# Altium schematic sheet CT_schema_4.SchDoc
size 316 x 185 mm
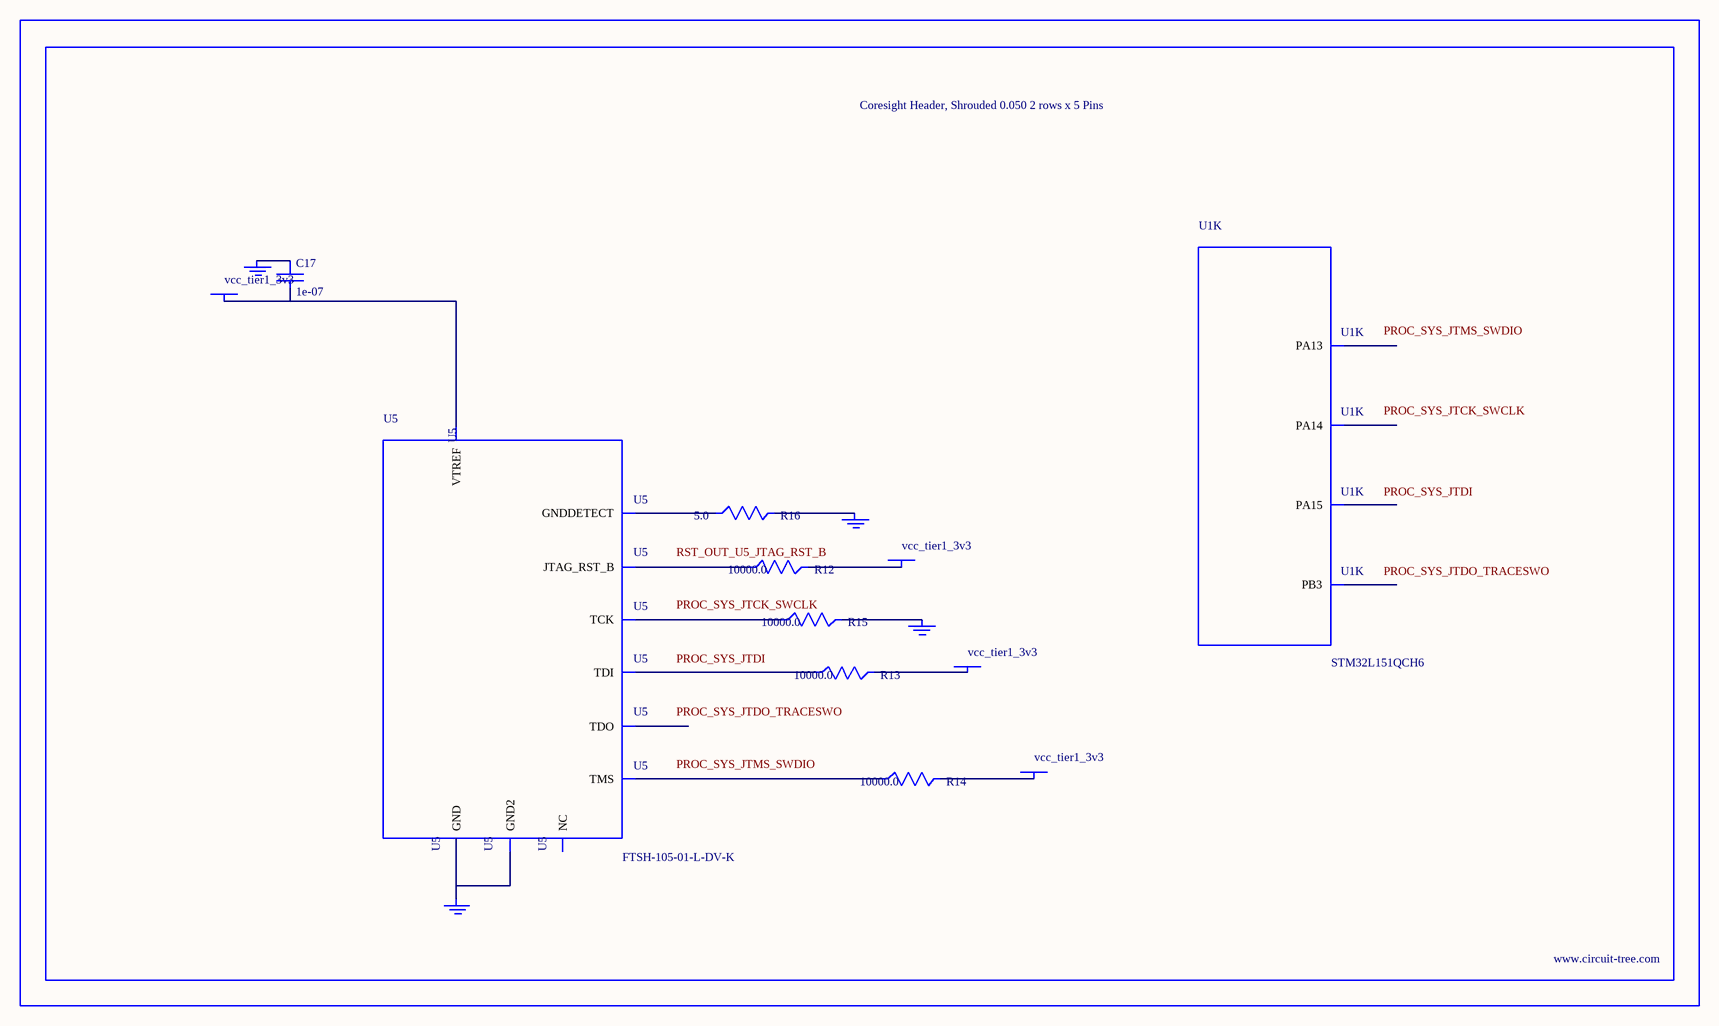
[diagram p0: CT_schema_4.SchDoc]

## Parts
BORDER3  (no value)
C17  1e-07  [C0402]
GND_INSTANCE_3_0  (no value)
GND_INSTANCE_3_1  (no value)
GND_INSTANCE_3_2  (no value)
GND_INSTANCE_3_3  (no value)
POWER_INSTANCE_3_0  vcc_tier1_3v3
POWER_INSTANCE_3_1  vcc_tier1_3v3
POWER_INSTANCE_3_2  vcc_tier1_3v3
POWER_INSTANCE_3_3  vcc_tier1_3v3
R12  10000.0  [R0603]
R13  10000.0  [R0603]
R14  10000.0  [R0603]
R15  10000.0  [R0603]
R16  5.0  [R0603]
U1  STM32L151QCH6  [UFBGA132]  (part K of 12)
U5  FTSH-105-01-L-DV-K  [SAMTEC_FTSH-105-01-L-DV-K]

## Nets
NetC17_1: C17.1 GND_INSTANCE_3_0.0(GND)
NetC17_2: C17.2 POWER_INSTANCE_3_0.0(PWR) U5.1(VTREF)
NetGND_INSTANCE_3_1_0: GND_INSTANCE_3_1.0(GND) R15.2
NetGND_INSTANCE_3_2_0: GND_INSTANCE_3_2.0(GND) R16.2
NetGND_INSTANCE_3_3_0: GND_INSTANCE_3_3.0(GND) U5.3(GND) U5.5(GND2)
NetPOWER_INSTANCE_3_1_0: POWER_INSTANCE_3_1.0(PWR) R14.2
NetPOWER_INSTANCE_3_2_0: POWER_INSTANCE_3_2.0(PWR) R13.2
NetPOWER_INSTANCE_3_3_0: POWER_INSTANCE_3_3.0(PWR) R12.2
NetR12_1: R12.1 U5.10(JTAG_RST_B)
NetR13_1: R13.1 U5.8(TDI)
NetR14_1: R14.1 U5.2(TMS)
NetR15_1: R15.1 U5.4(TCK)
NetR16_1: R16.1 U5.9(GNDDETECT)

Not connected (* = marked no-connect by the designer): U1 A8(PB3) A9(PA15) A10(PA14) A11(PA13); U5 6(TDO) 7(NC)

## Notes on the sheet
- Labels drawn without touching a wire or pin: PROC_SYS_JTCK_SWCLK, PROC_SYS_JTDI, PROC_SYS_JTDO_TRACESWO, PROC_SYS_JTMS_SWDIO, RST_OUT_U5_JTAG_RST_B

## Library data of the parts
BORDER3 = BORDER_PAGE3
C17 = C0402C104K3RACTU
GND_INSTANCE_3_0-GND_INSTANCE_3_3 = GND
POWER_INSTANCE_3_0-POWER_INSTANCE_3_3 = PWR
R12-R15 = RC0603JR-0710KL
R16 = ERJ-3GEYJ5R1V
